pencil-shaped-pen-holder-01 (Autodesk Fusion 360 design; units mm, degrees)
sketch "Sketch Base Profile" plane through (0, 0, 0) normal (0, 0, 1) x axis (1, 0, 0)
  line L1 (42.5, 0) -> (21.25, -36.8061)
  line L2 (21.25, 36.8061) -> (42.5, 0)
  line L3 (-21.25, 36.8061) -> (21.25, 36.8061)
  line L4 (-42.5, 0) -> (-21.25, 36.8061)
  line L5 (-21.25, -36.8061) -> (-42.5, 0)
  line L6 (21.25, -36.8061) -> (-21.25, -36.8061)
  line L7 (-18.3632, 31.8061) -> (18.3632, 31.8061)
  line L8 (-36.7265, 0) -> (-18.3632, 31.8061)
  line L9 (-18.3632, -31.8061) -> (-36.7265, 0)
  line L10 (18.3632, -31.8061) -> (-18.3632, -31.8061)
  line L11 (36.7265, 0) -> (18.3632, -31.8061)
  line L12 (18.3632, 31.8061) -> (36.7265, 0)
  line L13 (-19.8066, 34.3061) -> (19.8066, 34.3061)
  line L14 (-39.6132, 0) -> (-19.8066, 34.3061)
  line L15 (-19.8066, -34.3061) -> (-39.6132, 0)
  line L16 (19.8066, -34.3061) -> (-19.8066, -34.3061)
  line L17 (39.6132, 0) -> (19.8066, -34.3061)
  line L18 (19.8066, 34.3061) -> (39.6132, 0)
  line L19 (-21.25, 36.8061) -> (-21.25, -36.8061)
  line L20 (21.25, 36.8061) -> (21.25, -36.8061)
  circle C1 centre (0, 0) radius 20
  point P1 (0, 0)
  point P8 (0, 0)
  point P21 (0, 0)
  point P3 (42.5, 0)
  point P6 (-42.5, 0)
  coincident P1 P8
  horizontal L6
  coincident P8 P21
  dimension "bottomDaimeter" distance P3 P6 = 85
  dimension "wallThickness" = -5
  dimension "d3" = -2.5 (= "wallThickness / 2")
  dimension "d122" diameter C1 = 40
extrude "Extrude1" new body sketch "Sketch Base Profile" profile of L1 L2 L3 L4 L5 L6 L10 L9 L7 L11 L8 L12 L16 L15 L13 L17 L14 L18 L19 L20 along normal blind 105 named "height"
sketch "Sketch1 Cutting Tool" plane through (0, 0, 0) normal (1, 0, 0) x axis (0, 1, 0)
  line L1 (-42.5, 61.4073) -> (-30, 105)
  line L2 (0, 105) -> (0, 0.3854)
  line L3 (-42.5, 105) -> (-42.5, 61.4073)
  line L4 (-36.8061, 105) -> (-42.5, 105)
  line L5 (0, 105) -> (-36.8061, 105)
  line L6 (36.8061, 105) -> (0, 105)
  line L7 (0, 105) -> (36.8061, 105)
  line L8 (-36.8061, 105) -> (0, 105)
  point P7 (-36.8061, 105)
  point P8 (-36.8061, 105)
  point P3 (-42.5, 61.4073)
  point P6 (-42.5, 105)
  point P5 (0, 105)
  point P9 (0, 105)
  point P2 (-30, 105)
  coincident P7 P8
  perpendicular L3 L4
  vertical P3 P6
  coincident P5 P9
  coincident P2 L8
  dimension "d43" distance P2 P5 = 30
  dimension "d46" distance P3 L2 = 42.5 (= "bottomDaimeter / 2")
  dimension "d101" angle L1 L3 = 16
revolve "Revolve1" sketch "Sketch1 Cutting Tool" AlongAngle 360
extrude "Extrude1" new body of existing geometry blind -2.5 (= "wallThickness / 2")
circular_pattern "C-Pattern1" TotalAngle 360
combine "Combine1"
fillet "Fillet1" radius 5 3
combine "Combine1"
sketch "Sketch Top insert" plane through (0, 0, 105) normal (0, 0, 1) x axis (-1, 0, 0)
  circle C1 centre (0, 0) radius 30
  circle C2 centre (0, 0) radius 25
  dimension "d115" = -5 (= "wallThickness")
extrude "Extrude2" cut sketch "Sketch Top insert" profile of C2 against normal blind 5 (magnitude of "wallThickness")
shell "Shell1" innerThickness 2.5 (= "-wallThickness / 2")
offset_faces "OffsetFaces1" distance 2.5
offset_faces "OffsetFaces2" distance 2.5 (= "-wallThickness / 2")
extrude "Extrude2" new body sketch "Sketch Base Profile" profile of C1 to an object
combine "Combine2"
chamfer "Chamfer2" distance 2
chamfer "Chamfer3" distance 14.3 Rotate Angle 15
sketch "Sketch1" plane through (0, 0, 0) normal (0, 0, 1) x axis (1, 0, 0)
  line L1 (4.0415, 0) -> (2.0207, -3.5)
  line L2 (2.0207, 3.5) -> (4.0415, 0)
  line L3 (-2.0207, 3.5) -> (2.0207, 3.5)
  line L4 (-4.0415, 0) -> (-2.0207, 3.5)
  line L5 (-2.0207, -3.5) -> (-4.0415, 0)
  line L6 (2.0207, -3.5) -> (-2.0207, -3.5)
  line L7 (-1.963, 3.4) -> (1.963, 3.4)
  line L8 (-3.926, 0) -> (-1.963, 3.4)
  line L9 (-1.963, -3.4) -> (-3.926, 0)
  line L10 (1.963, -3.4) -> (-1.963, -3.4)
  line L11 (3.926, 0) -> (1.963, -3.4)
  line L12 (1.963, 3.4) -> (3.926, 0)
  circle C1 centre (0, 0) radius 2.5
  point P1 (0, 0)
  point P8 (0, 0)
  point P15 (0, 0)
  coincident P1 P8
  horizontal L6
  coincident P1 P15
  dimension "d1" distance L1 L4 = 7
  dimension "d2" = -0.1
  dimension "d3_1" distance L6 C1 = 1
extrude "Extrude1" new body sketch "Sketch1" profile of C1 along normal blind 170
extrude "Extrude1" new body sketch "Sketch1" profile of L10 L9 L7 L11 L8 L12 C1 along normal blind 170
extrude "Extrude2" new body sketch "Sketch1" profile of L1 L2 L3 L4 L5 L6 L10 L9 L7 L11 L8 L12 along normal blind 170
sketch "Sketch2" plane through (0, 0, 0) normal (0, 1, 0) x axis (1, 0, 0)
  line L1 (2.5, -170) -> (-2.5, -170)
  line L2 (4.0415, -153.7906) -> (0, -170)
  line L3 (0, -153.7906) -> (0, -170)
  line L4 (4.0415, -170) -> (0, -170)
  line L5 (4.0415, -170) -> (4.0415, -153.7906)
  point P4 (0, -170)
  point P5 (4.0415, -153.7906)
  point P6 (0, -153.7906)
  point P7 (4.0415, -170)
  point P8 (4.0415, -170)
  point P9 (4.0415, -170)
  midpoint L1 P4
  perpendicular L1 L3
  horizontal P5 P6
  coincident P7 P8
  vertical P5 P7
  coincident P8 P9
  dimension "d10" angle L2 L3 = 14
revolve "Revolve1" sketch "Sketch2" AlongAngle 360
position "Position1"
circular_pattern "C-Pattern2" TotalAngle 360
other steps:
revolve "Revolve1" sketch "Sketch2" AlongAngle 360
circular_pattern "C-Pattern1" TotalAngle 360
fillet "Fillet1" radius 5
create_component "CreateComponent6"
create_component "CreateComponent7"
create_component "CreateComponent8"
create_component "CreateComponent1"
create_component "CreateComponent2"
create_component "CreateComponent1"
